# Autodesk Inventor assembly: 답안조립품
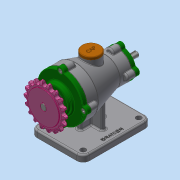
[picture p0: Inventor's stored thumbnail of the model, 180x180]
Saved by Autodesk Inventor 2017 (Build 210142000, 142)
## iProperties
Part Number: 답안조립품
Material: 일반
Document SubType Name: Assembly
Designer: JiNi
Author: JiNi
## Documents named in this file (15)
- C:\Users\JiNi\Desktop\701206V1018\답안조립품.iam
- C:\Users\JiNi\Desktop\701206V1018\본체.ipt
- C:\Users\JiNi\Desktop\701206V1018\축.ipt
- C:\Users\JiNi\Desktop\701206V1018\앞커버.ipt
- C:\Users\JiNi\Desktop\701206V1018\오일 실 17 30 8.ipt
- C:\Users\JiNi\Desktop\701206V1018\베어링 6203.ipt
- C:\Users\JiNi\Desktop\701206V1018\개스킷 A.ipt
- C:\Users\JiNi\Desktop\701206V1018\볼트 M5.ipt
- C:\Users\JiNi\Desktop\701206V1018\개스킷 B.ipt
- C:\Users\JiNi\Desktop\701206V1018\뒤커버.ipt
- C:\Users\JiNi\Desktop\701206V1018\베어링 6200.ipt
- C:\Users\JiNi\Desktop\701206V1018\오일 실 10 20 7.ipt
- C:\Users\JiNi\Desktop\701206V1018\키 4x4x14.ipt
- C:\Users\JiNi\Desktop\701206V1018\스프로킷.ipt
- C:\Users\JiNi\Desktop\701206V1018\마개.ipt
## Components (2 placed, 2 different names)
1. 개스킷 A:1
2. 개스킷 B:1
